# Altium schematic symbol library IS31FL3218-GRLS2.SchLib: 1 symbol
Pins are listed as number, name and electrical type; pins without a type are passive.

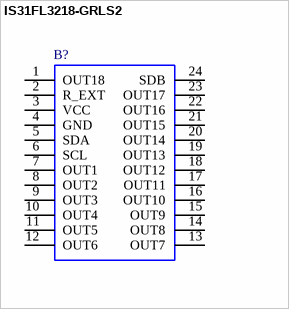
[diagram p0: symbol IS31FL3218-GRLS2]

## IS31FL3218-GRLS2
designator B?
IC LED DRIVER 18CH CC PWM 24SOIC; Manufacturer_Name: Lumissil; Geometry.Height: 2.65mm
footprint SOIC127P1036X265-24N
pins: 1 OUT18, 2 R_EXT, 3 VCC, 4 GND, 5 SDA, 6 SCL, 7 OUT1, 8 OUT2, 9 OUT3, 10 OUT4, 11 OUT5, 12 OUT6, 13 OUT7, 14 OUT8, 15 OUT9, 16 OUT10, 17 OUT11, 18 OUT12, 19 OUT13, 20 OUT14, 21 OUT15, 22 OUT16, 23 OUT17, 24 SDB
